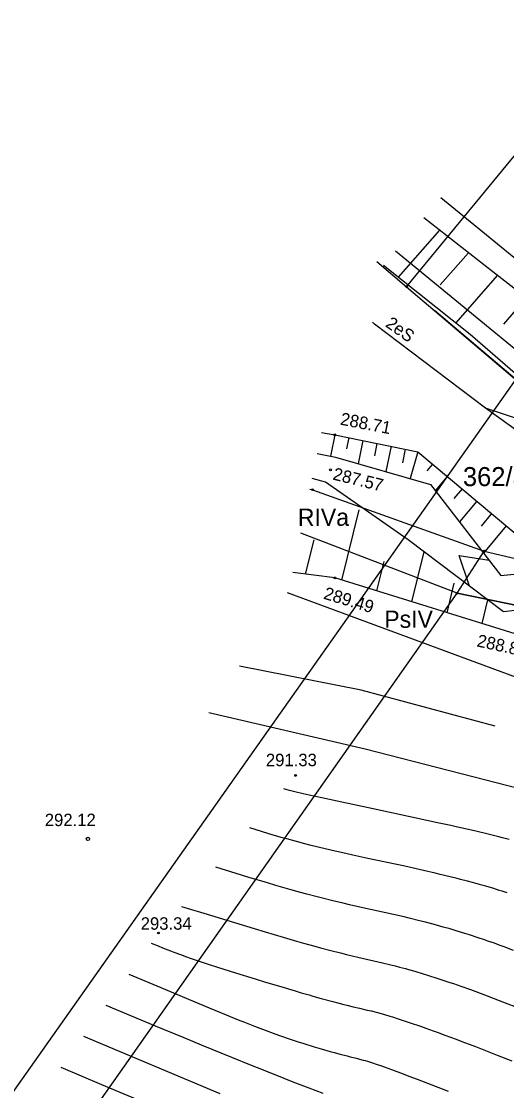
# Model space of a CAD drawing. Extents: x 7477803 to 7478145, y 5500698 to 5500984.
# Drawn here: x 7477856.6 to 7477883.1, y 5500892.7 to 5500951.1 of the extents above; entities that cross this region are included whole.
import ezdxf

# ---------------------------------------------------------------- set-up
doc = ezdxf.new("R2010")
doc.units = 0
for name, color, linetype in [('203-Punkt załamania granicy działki nie stabilizowany', 7, 'Continuous'), ('e_opisy', 7, 'Continuous'), ('eNN', 7, 'Continuous'), ('eWN', 7, 'Continuous'), ('gr_dzialki', 7, 'Continuous'), ('gr_klasy', 7, 'Continuous'), ('jezdnia', 7, 'Continuous'), ('nr_dzialki', 7, 'Continuous'), ('ogr_symb', 7, 'Continuous'), ('opis_klasy', 7, 'Continuous'), ('pkt_wys', 7, 'Continuous'), ('rowy', 7, 'Continuous'), ('skarp_wypel', 7, 'Continuous'), ('skarpa_gora', 7, 'Continuous'), ('warst_ciagla', 7, 'Continuous'), ('warst_pogrub', 7, 'Continuous'), ('warst_przeryw', 7, 'Continuous'), ('zakresy', 7, 'Continuous')]:
    doc.layers.add(name, color=color, linetype=linetype)

# ---------------------------------------------------------------- blocks, each defined once
blk = doc.blocks.new('203')
blk.add_circle((0, 0), 0.045)
blk = doc.blocks.new('801_3')
at = {"layer": 'pkt_wys'}
blk.add_circle((0, 0), 0.045, dxfattribs=at)
blk.add_circle((0, 0), 0.045, dxfattribs=at)
blk = doc.blocks.new('801_5')
at = {"layer": 'pkt_wys'}
blk.add_circle((0, 0), 0.05, dxfattribs=at)
blk.add_circle((0, 0), 0.05, dxfattribs=at)

msp = doc.modelspace()

# ---------------------------------------------------------------- linework, layer by layer
at = {"layer": 'eNN'}
msp.add_lwpolyline([(7477908.551, 5500910.148), (7477905.276, 5500912.813), (7477899.85, 5500917.156), (7477893.431, 5500922.355), (7477885.497, 5500928.781), (7477881.972, 5500929.954)], dxfattribs=at)
at = {"layer": 'eWN'}
msp.add_lwpolyline([(7477864.586, 5500830.869), (7477874.504, 5500845.51), (7477886.717, 5500863.094), (7477896.968, 5500876.013), (7477903.181, 5500887.651), (7477907.573, 5500896.009), (7477910.052, 5500901.721), (7477911.094, 5500907.132), (7477899.209, 5500916.554), (7477885.259, 5500927.591), (7477881.972, 5500929.954), (7477875.911, 5500934.547), (7477875.795, 5500934.654)], dxfattribs=at)
at = {"layer": 'gr_dzialki'}
for points in [[(7477877.66, 5500936.58), (7477886.94, 5500947.84)], [(7477876.036, 5500937.958), (7477877.66, 5500936.58)], [(7477877.66, 5500936.58), (7477902.05, 5500915.88)], [(7477872.375, 5500925.536), (7477872.52, 5500925.51)], [(7477872.52, 5500925.51), (7477881.9, 5500922.16)], [(7477880.41, 5500919.86), (7477881.9, 5500922.16)], [(7477843.04, 5500866.8), (7477880.41, 5500919.86)], [(7477880.41, 5500919.86), (7477899.54, 5500915.94)]]:
    msp.add_lwpolyline(points, dxfattribs=at)
at = {"layer": 'gr_klasy'}
for points in [[(7477898.94, 5500918.55), (7477879.178, 5500935.294)], [(7477872.375, 5500925.536), (7477872.52, 5500925.51)], [(7477872.52, 5500925.51), (7477881.9, 5500922.16)], [(7477880.41, 5500919.86), (7477871.884, 5500923.145)], [(7477880.41, 5500919.86), (7477881.9, 5500922.16)], [(7477881.9, 5500922.16), (7477890.12, 5500920.23)], [(7477893.15, 5500911.75), (7477871.161, 5500919.882)], [(7477899.54, 5500915.94), (7477880.41, 5500919.86)]]:
    msp.add_lwpolyline(points, dxfattribs=at)
at = {"layer": 'jezdnia'}
msp.add_lwpolyline([(7477893.479, 5500930.51), (7477883.411, 5500938.249), (7477879.53, 5500941.424)], dxfattribs=at)
at = {"layer": 'ogr_symb'}
msp.add_lwpolyline([(7477888.491, 5500929.144), (7477877.044, 5500938.519)], dxfattribs=at)
at = {"layer": 'pkt_wys'}
msp.add_circle((7477860.256, 5500906.461), 0.09, dxfattribs=at)
at = {"layer": 'rowy'}
for points in [[(7477872.777, 5500927.493), (7477873.773, 5500927.288), (7477878.954, 5500925.794), (7477882.8, 5500920.838), (7477884.259, 5500920.969), (7477889.475, 5500925.025), (7477890.824, 5500925.587), (7477895.037, 5500923.381), (7477901.802, 5500918.709), (7477903.365, 5500919.391)], [(7477904.573, 5500918.501), (7477902.695, 5500916.13), (7477893.838, 5500922.21), (7477890.767, 5500923.127), (7477884.852, 5500919.07), (7477882.952, 5500918.848), (7477877.738, 5500922.782), (7477873.234, 5500925.927), (7477872.495, 5500926.12)], [(7477881.091, 5500920.252), (7477880.525, 5500921.931), (7477882.157, 5500921.665)]]:
    msp.add_lwpolyline(points, dxfattribs=at)
at = {"layer": 'skarp_wypel'}
for p, q in [((7477879.453, 5500939.673), (7477877.204, 5500937.112)), ((7477881.028, 5500938.435), (7477879.496, 5500936.691)), ((7477882.604, 5500937.199), (7477880.34, 5500934.62)), ((7477884.186, 5500935.97), (7477882.938, 5500934.549)), ((7477873.731, 5500928.508), (7477873.494, 5500927.345)), ((7477874.5, 5500928.351), (7477874.376, 5500927.743)), ((7477875.269, 5500928.194), (7477875.011, 5500926.931)), ((7477876.038, 5500928.037), (7477875.9, 5500927.363)), ((7477876.807, 5500927.88), (7477876.524, 5500926.495)), ((7477877.576, 5500927.723), (7477877.425, 5500926.983)), ((7477878.262, 5500927.583), (7477877.852, 5500926.13)), ((7477879.069, 5500926.91), (7477878.757, 5500926.537)), ((7477879.875, 5500926.237), (7477879.22, 5500925.452)), ((7477880.681, 5500925.564), (7477880.238, 5500925.033)), ((7477881.488, 5500924.891), (7477880.538, 5500923.753)), ((7477874.121, 5500920.58), (7477875.063, 5500924.406)), ((7477882.294, 5500924.218), (7477881.719, 5500923.529)), ((7477883.1, 5500923.545), (7477881.856, 5500922.054)), ((7477872.142, 5500920.905), (7477872.601, 5500922.77)), ((7477877.949, 5500919.395), (7477878.619, 5500922.117)), ((7477876.035, 5500919.988), (7477876.429, 5500921.588)), ((7477879.863, 5500918.803), (7477880.257, 5500920.405)), ((7477881.777, 5500918.211), (7477882.093, 5500919.496))]:
    msp.add_line(p, q, dxfattribs=at)
at = {"layer": 'skarpa_gora'}
for points in [[(7477892.66, 5500929.389), (7477882.362, 5500937.387), (7477878.603, 5500940.34)], [(7477876.391, 5500937.758), (7477881.125, 5500933.996), (7477890.824, 5500925.587)], [(7477873.01, 5500928.626), (7477873.731, 5500928.508), (7477878.262, 5500927.583), (7477884.078, 5500922.729), (7477889.475, 5500925.025)], [(7477873.74, 5500920.698), (7477871.442, 5500920.996)], [(7477884.64, 5500917.325), (7477873.74, 5500920.698)]]:
    msp.add_lwpolyline(points, dxfattribs=at)
at = {"layer": 'warst_ciagla'}
for points in [[(7477884.531, 5500909.018), (7477875.396, 5500911.354), (7477875.396, 5500911.354), (7477866.858, 5500913.345)], [(7477883.153, 5500903.516), (7477882.866, 5500903.609), (7477882.718, 5500903.656), (7477882.412, 5500903.75), (7477881.986, 5500903.877), (7477881.764, 5500903.94), (7477881.246, 5500904.084), (7477880.976, 5500904.156), (7477880.606, 5500904.253), (7477880.416, 5500904.301), (7477880.028, 5500904.399), (7477879.49, 5500904.53), (7477879.213, 5500904.595), (7477878.57, 5500904.744), (7477877.562, 5500904.968), (7477875.549, 5500905.402), (7477874.728, 5500905.582), (7477874.334, 5500905.67), (7477873.756, 5500905.801), (7477872.901, 5500906), (7477872.38, 5500906.125), (7477872.101, 5500906.195), (7477871.64, 5500906.316), (7477871.109, 5500906.462), (7477870.809, 5500906.547), (7477870.129, 5500906.746), (7477869.743, 5500906.862), (7477869.098, 5500907.06)], [(7477865.376, 5500902.782), (7477866.947, 5500902.298), (7477867.847, 5500902.022), (7477869.333, 5500901.57), (7477869.937, 5500901.388), (7477870.913, 5500901.097), (7477871.641, 5500900.885), (7477872.024, 5500900.777), (7477872.642, 5500900.607), (7477872.95, 5500900.525), (7477873.521, 5500900.375), (7477874.042, 5500900.242), (7477874.369, 5500900.162), (7477874.99, 5500900.014), (7477876.337, 5500899.707), (7477876.796, 5500899.597), (7477877.031, 5500899.538), (7477877.27, 5500899.476), (7477877.597, 5500899.388), (7477877.763, 5500899.341), (7477878.102, 5500899.244), (7477878.567, 5500899.105), (7477878.806, 5500899.032), (7477879.355, 5500898.857), (7477879.637, 5500898.765), (7477880.021, 5500898.636), (7477880.215, 5500898.57), (7477880.611, 5500898.432), (7477881.152, 5500898.24), (7477881.428, 5500898.139), (7477882.063, 5500897.904), (7477882.387, 5500897.782), (7477883.044, 5500897.529), (7477883.703, 5500897.273)], [(7477862.489, 5500899.084), (7477864.013, 5500898.444), (7477866.306, 5500897.486), (7477866.88, 5500897.248), (7477867.797, 5500896.871), (7477868.466, 5500896.6), (7477868.81, 5500896.463), (7477869.349, 5500896.252), (7477870.089, 5500895.972), (7477870.513, 5500895.816), (7477870.771, 5500895.723), (7477871.245, 5500895.558), (7477871.733, 5500895.397), (7477872.038, 5500895.3), (7477872.604, 5500895.127), (7477872.998, 5500895.01), (7477873.483, 5500894.87), (7477873.709, 5500894.807), (7477874.026, 5500894.721), (7477874.409, 5500894.622), (7477874.584, 5500894.579), (7477874.915, 5500894.5), (7477875.091, 5500894.456), (7477875.289, 5500894.401), (7477875.399, 5500894.369), (7477875.519, 5500894.332), (7477875.694, 5500894.277), (7477875.788, 5500894.246), (7477875.988, 5500894.179), (7477876.282, 5500894.078), (7477876.44, 5500894.022), (7477876.824, 5500893.884), (7477877.471, 5500893.646), (7477877.787, 5500893.527), (7477878.234, 5500893.357), (7477878.469, 5500893.267), (7477879.025, 5500893.052), (7477879.924, 5500892.701)]]:
    msp.add_lwpolyline(points, dxfattribs=at)
at = {"layer": 'warst_pogrub'}
msp.add_lwpolyline([(7477867.484, 5500892.551), (7477860.032, 5500895.685)], dxfattribs=at)
at = {"layer": 'warst_przeryw'}
for points in [[(7477882.485, 5500912.604), (7477875.173, 5500914.57), (7477868.526, 5500915.879)], [(7477883.262, 5500906.427), (7477882.887, 5500906.525), (7477882.684, 5500906.576), (7477882.191, 5500906.697), (7477881.356, 5500906.895), (7477880.947, 5500906.989), (7477880.368, 5500907.12), (7477880.063, 5500907.188), (7477879.34, 5500907.347), (7477878.174, 5500907.598), (7477875.829, 5500908.096), (7477873.874, 5500908.514), (7477873.03, 5500908.696), (7477872.331, 5500908.851), (7477872.004, 5500908.925), (7477871.547, 5500909.036), (7477871.27, 5500909.108), (7477871.141, 5500909.144), (7477870.959, 5500909.198)], [(7477883.495, 5500900.384), (7477882.974, 5500900.579), (7477882.711, 5500900.675), (7477882.448, 5500900.77), (7477882.095, 5500900.893), (7477881.918, 5500900.954), (7477881.562, 5500901.074), (7477881.084, 5500901.229), (7477880.844, 5500901.304), (7477880.301, 5500901.47), (7477880.027, 5500901.551), (7477879.661, 5500901.656), (7477879.477, 5500901.708), (7477879.108, 5500901.809), (7477878.613, 5500901.939), (7477878.364, 5500902.003), (7477877.8, 5500902.141), (7477877.517, 5500902.208), (7477876.949, 5500902.338), (7477875.27, 5500902.708), (7477874.548, 5500902.872), (7477874.188, 5500902.956), (7477873.638, 5500903.088), (7477873.068, 5500903.229), (7477872.771, 5500903.304), (7477872.202, 5500903.451), (7477871.871, 5500903.54), (7477871.277, 5500903.707), (7477870.523, 5500903.925), (7477870.071, 5500904.059), (7477868.988, 5500904.384), (7477868.345, 5500904.58), (7477867.237, 5500904.921)], [(7477863.718, 5500900.784), (7477864.101, 5500900.624), (7477864.336, 5500900.529), (7477864.761, 5500900.36), (7477864.955, 5500900.285), (7477865.31, 5500900.153), (7477865.633, 5500900.037), (7477865.836, 5500899.967), (7477866.227, 5500899.836), (7477866.886, 5500899.62), (7477867.339, 5500899.474), (7477868.313, 5500899.165), (7477869.396, 5500898.829), (7477869.957, 5500898.656), (7477870.787, 5500898.405), (7477871.574, 5500898.171), (7477871.908, 5500898.074), (7477872.337, 5500897.95), (7477872.544, 5500897.891), (7477872.996, 5500897.765), (7477873.63, 5500897.593), (7477873.896, 5500897.522), (7477874.235, 5500897.435), (7477874.398, 5500897.394), (7477874.747, 5500897.309), (7477875.077, 5500897.231), (7477875.506, 5500897.13), (7477875.726, 5500897.077), (7477876.074, 5500896.987), (7477876.261, 5500896.935), (7477876.457, 5500896.879), (7477876.736, 5500896.796), (7477876.882, 5500896.751), (7477877.189, 5500896.655), (7477877.627, 5500896.511), (7477877.859, 5500896.434), (7477878.41, 5500896.244), (7477878.702, 5500896.141), (7477879.107, 5500895.996), (7477879.317, 5500895.92), (7477879.75, 5500895.761), (7477880.357, 5500895.535), (7477880.673, 5500895.416), (7477881.414, 5500895.133), (7477882.593, 5500894.675), (7477883.395, 5500894.36)], [(7477873.098, 5500892.584), (7477872.345, 5500892.864), (7477871.467, 5500893.2), (7477870.969, 5500893.394), (7477869.836, 5500893.842), (7477869.192, 5500894.101), (7477868.115, 5500894.537), (7477866.451, 5500895.22), (7477865.512, 5500895.608), (7477863.955, 5500896.255), (7477861.261, 5500897.385)], [(7477864.321, 5500891.672), (7477861.017, 5500893.055), (7477858.804, 5500893.986)]]:
    msp.add_lwpolyline(points, dxfattribs=at)
at = {"layer": 'zakresy'}
msp.add_lwpolyline([(7477995.059, 5500962.348), (7477983.951, 5500968.084), (7477970.781, 5500968.613), (7477936.09, 5500958.171), (7477930.511, 5500954.336), (7477914.305, 5500958.58), (7477904.32, 5500957.41), (7477897.265, 5500950.868), (7477811.424, 5500829.338), (7477936.003, 5500769.492), (7478008.982, 5500726.585), (7478019.402, 5500721.781), (7478037.95, 5500734.97), (7478039.493, 5500755.094), (7478043.98, 5500765.708), (7478067.545, 5500795.068), (7478092.109, 5500820.25), (7478076.156, 5500837.989), (7478068.105, 5500851.146), (7478061.422, 5500873.298), (7478054.135, 5500876.371), (7478039.669, 5500897.644), (7478026.36, 5500915.23), (7478015.054, 5500927.728)], close=True, dxfattribs=at)

# ---------------------------------------------------------------- block references
at = {"layer": '203-Punkt załamania granicy działki nie stabilizowany'}
for p in [(7477877.66, 5500936.58), (7477872.52, 5500925.51), (7477881.9, 5500922.16), (7477880.41, 5500919.86)]:
    msp.add_blockref('203', p, dxfattribs=at)
at = {"layer": 'pkt_wys', "rotation": 0.0626175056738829}
for name, p in [('801_5', (7477873.731, 5500928.508)), ('801_5', (7477873.503, 5500926.598)), ('801_5', (7477873.74, 5500920.698)), ('801_3', (7477871.592, 5500909.926)), ('801_3', (7477864.111, 5500901.327))]:
    msp.add_blockref(name, p, dxfattribs=at)

# ---------------------------------------------------------------- texts
at = {"layer": 'e_opisy'}
msp.add_text('2eS', height=0.68, rotation=324.72883, dxfattribs=at).set_placement((7477876.455, 5500934.445))
at = {"layer": 'nr_dzialki'}
msp.add_text('362/33', height=1.04, dxfattribs=at).set_placement((7477880.733, 5500925.705))
at = {"layer": 'opis_klasy'}
for s, p in [('RIVa', (7477871.718, 5500923.539)), ('PsIV', (7477876.439, 5500917.977))]:
    msp.add_text(s, height=0.94, dxfattribs=at).set_placement(p)
at = {"layer": 'pkt_wys'}
for s, rotation, p in [('288.71', 349.05214, (7477874, 5500929.065)), ('287.57', 346.23397, (7477873.587, 5500926.071)), ('289.49', 343.17583, (7477873.08, 5500919.573)), ('288.85', 347.73769, (7477881.455, 5500916.969)), ('291.33', 0.06262, (7477869.975, 5500910.429)), ('292.12', 0.06262, (7477857.905, 5500907.158)), ('293.34', 0.06262, (7477863.141, 5500901.508))]:
    msp.add_text(s, height=0.68, rotation=rotation, dxfattribs=at).set_placement(p)

doc.saveas('drawing.dxf')
